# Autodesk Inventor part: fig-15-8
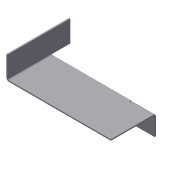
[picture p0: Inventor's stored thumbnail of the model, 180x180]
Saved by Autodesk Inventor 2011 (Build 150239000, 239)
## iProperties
Shininess: 77.0
Angle Display Precision: 2
Document Length Units: 11269
Document Angle Units: 11279
Document Time Units: 11290
Document Mass Units: 11283
Document Length Units Precision: 3
Document Angle Units Precision: 2
Created: 2002-04
Part Number: fig-15-8
Material: Aluminum-6061
Document SubType Name: Sheet Metal
Density: 1 g/cm^3
Sheet Metal Rule: Default
Density: 0.0
Volumn: 0.0
Area: 0.0
PropertySet Name: Model Information
Control State: 0
Master: False
Checked Out: False
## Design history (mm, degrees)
node "Face1"
  sketch "Sketch1"
    geometry: L1 (-49.559, 19.574)-(-49.559, -30.426); L2 (-49.559, -30.426)-(50.441, -30.426); L3 (50.441, -30.426)-(50.441, 19.574); L4 (50.441, 19.574)-(32.941, 19.574); L5 (32.941, 19.574)-(32.941, 4.574); L6 (32.941, 4.574)-(-32.059, 4.574); L7 (-32.059, 4.574)-(-32.059, 19.574); L8 (-32.059, 19.574)-(-49.559, 19.574)
    constraints: 16 end point, 6 parallel, 2 equal length, 1 perpendicular, 1 vertical
    dimensions: "d0" = 100 distance of L1.end L2.end; "d1" = 65 distance of L5.end L6.end; "d2" = 15 distance of L6.end L7.end; "d3" = 50 distance of L1.start L1.end
sketch "Sketch2"
  geometry: L1 (100, 0)-(0, 0) reference; L2 (17.5, 50)-(17.5, 35) reference; L3 (82.5, 50)-(82.5, 0)
  constraints: 2 end point, 1 parallel, 1 point on line
sketch "Sketch3"
  geometry: L1 (81.369, -50)-(0, -50) reference; L2 (17.5, 0)-(17.5, -50)
  constraints: 2 end point, 1 perpendicular, 1 point on line
feature "Fold2" sketch "Sketch3" dims "d8" = 1 (= BendRadius), "d9" = 90 deg, "d10" = 1 (= BendRadius), "d14" = 1 (= BendReliefWidth), "d15" = 0.5 (= BendReliefDepth), "d16" = 2 (= MinimumRemnant), "SeamGap" = 0.01, "Thickness" = 1
sketch "Sketch4"
  geometry: L1 (17.5, 0)-(17.5, -50) reference; L2 (-63.869, -15)-(0, -15) reference; L3 (0, -15)-(17.5, -15)
  constraints: 2 end point, 1 collinear, 1 point on line
feature "Fold3" sketch "Sketch4" dims "d11" = 1 (= BendRadius), "d12" = 90 deg, "d13" = 1 (= BendRadius), "d17" = 1 (= BendReliefWidth), "d18" = 0.5 (= BendReliefDepth), "d19" = 2 (= MinimumRemnant), "SeamGap" = 0.01, "Thickness" = 1
body "Solid1"
face "Plate1" dims "Thickness" = 1
other parameters: "BendRadius" = 1 (= Thickness), "BendReliefWidth" = 1 (= Thickness), "BendReliefDepth" = 0.5 (= 0.5 x Thickness), "CornerReliefSize" = 4 (= 4 x Thickness), "MinimumRemnant" = 2 (= 2 x Thickness), "TransitionRadius" = 1 (= BendRadius), "d4" = 1 (= BendRadius), "JacobiRadiusSize" = 1 (= Thickness), "GapSize" = 1 (= Thickness)
